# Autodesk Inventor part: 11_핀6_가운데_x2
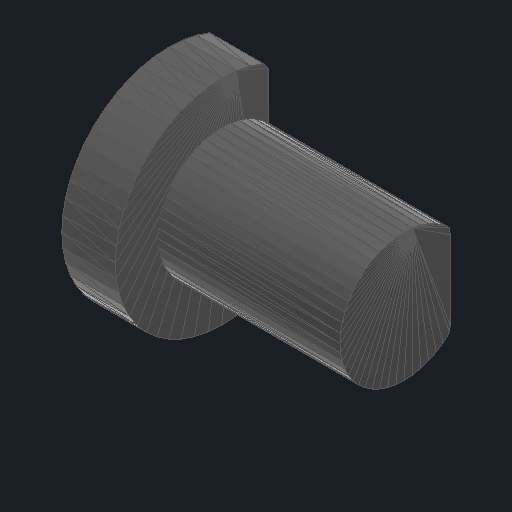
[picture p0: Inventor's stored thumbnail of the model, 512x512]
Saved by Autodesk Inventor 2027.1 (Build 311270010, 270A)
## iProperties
Created: 2026-11
Part Number: 11_핀6_가운데_x2
Material: 일반
Document SubType Name: Modeling
Designer: djshs
Density: 1 g/cm^3
Appearance: 기본값
Author: djshs
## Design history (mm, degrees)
node "11_핀6_가운데_x2"
  node "MeshFeature1"
